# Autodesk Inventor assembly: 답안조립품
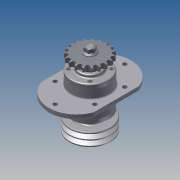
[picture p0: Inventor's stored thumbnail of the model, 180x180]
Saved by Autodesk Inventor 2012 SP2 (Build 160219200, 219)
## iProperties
Created: 2015-02
Part Number: 답안조립품
Document SubType Name: Assembly
Designer: Administrator
Author: Administrator
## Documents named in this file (12)
- C:\Users\Administrator\Desktop\450208V1004\답안조립품.iam
- C:\Users\Administrator\Desktop\450208V1004\본체.ipt
- C:\Users\Administrator\Desktop\450208V1004\2-커버.ipt
- C:\Users\Administrator\Desktop\450208V1004\3-축.ipt
- C:\Users\Administrator\Desktop\450208V1004\4-V벨트풀리.ipt
- C:\Users\Administrator\Desktop\450208V1004\5-체인 스프로킷.ipt
- C:\Users\Administrator\Desktop\450208V1004\6-베어링 6206.ipt
- C:\Users\Administrator\Desktop\450208V1004\7-부시.ipt
- C:\Users\Administrator\Desktop\450208V1004\8-오일실 30x42.ipt
- C:\Users\Administrator\Desktop\450208V1004\9-M16-너트.ipt
- C:\Users\Administrator\Desktop\450208V1004\10-M6.ipt
- C:\Users\Administrator\Desktop\450208V1004\11-키 6x6.ipt
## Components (22 placed, 10 different names)
1. 2-커버:1
2. 2-커버:2
3. 3-축:1
4. 4-V벨트풀리:1
5. 5-체인 스프로킷:1
6. 6-베어링 6206:1
7. 6-베어링 6206:2
8. 7-부시:1
9. 8-8-오일실 30x42:1
10. 8-8-오일실 30x42:2
11. 9-M16 너트:1
12. 9-M16 너트:2
13. 11-키 6x6:1
14. 11-키 6x6:2
15. 10-M6:1
16. 10-M6:3
17. 10-M6:4
18. 10-M6:5
19. 10-M6:2
20. 10-M6:6
21. 10-M6:7
22. 10-M6:8
